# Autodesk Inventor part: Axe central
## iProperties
Author: Philippe
Created: 2002-01
Part Number: Axe central
Material: Par défaut
Document SubType Name: Modélisation
Designer: Philippe
Control State: 0
Master: False
Checked Out: False
PropertySet Name: Design Tracking Control
Shininess: 60.0
Angle Display Precision: 2
Document Length Units: 11269
Document Angle Units: 11283
Document Time Units: 11279
Document Mass Units: 11290
Document Length Units Precision: 3
Document Angle Units Precision: 2
Compacted: False
PropertySet Name: _Private Model Information
Density: 0.0
Volumn: 0.0
Area: 0.0
PropertySet Name: Model Information
